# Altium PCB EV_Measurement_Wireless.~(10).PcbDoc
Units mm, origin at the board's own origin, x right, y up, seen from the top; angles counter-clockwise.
Board outline 152.4 x 101.6 mm, 4 copper layers (Top Layer, Mid-Layer 1, Mid_Layer 2, Bottom Layer), stack 0.605 mm thick; 59 components, 41 nets, 407 pads, 56 vias.
Unrouted connection lines stored in the file: 245.
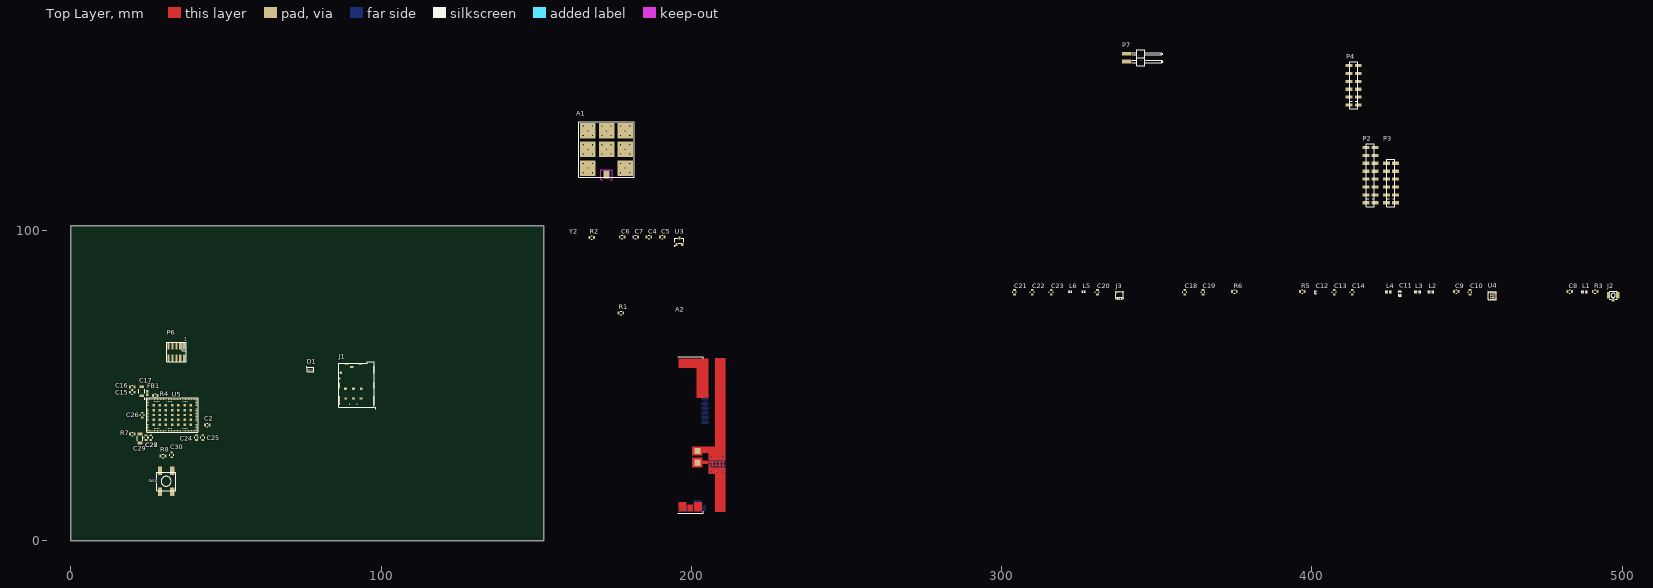
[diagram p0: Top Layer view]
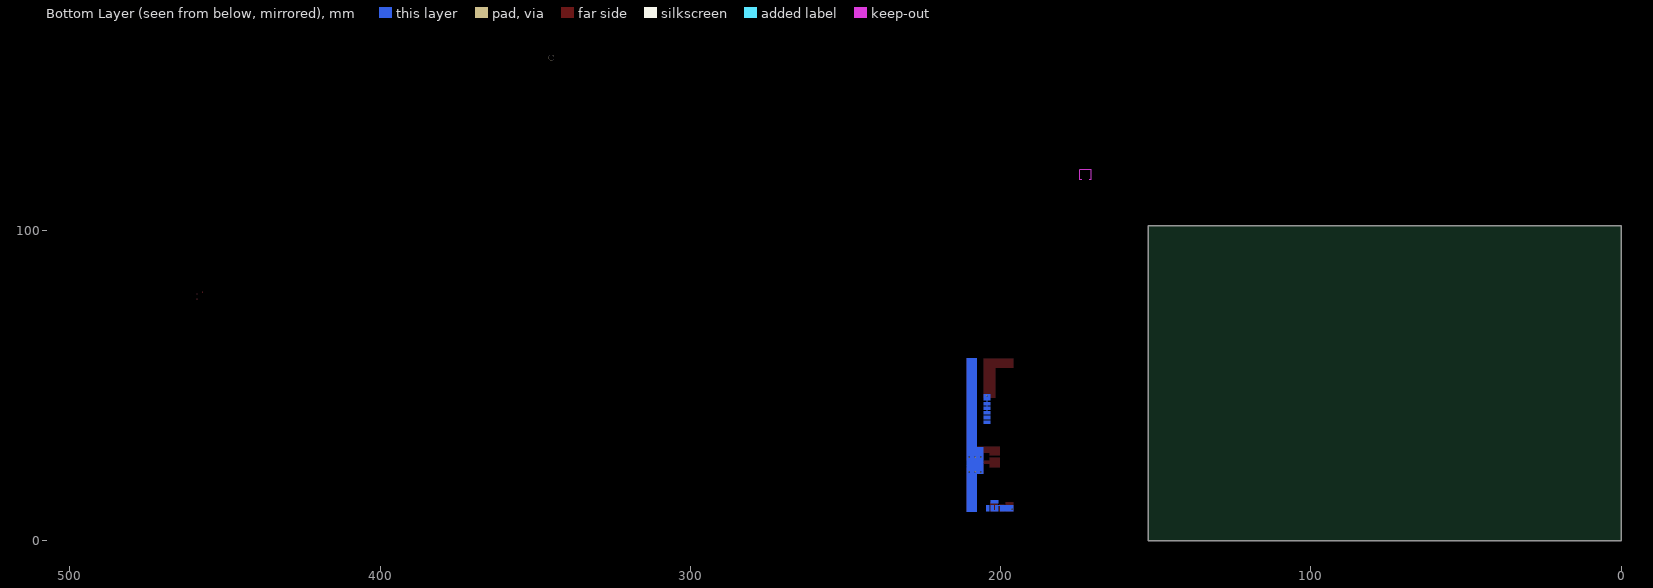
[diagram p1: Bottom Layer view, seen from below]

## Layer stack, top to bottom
Top Solder: solder mask 0.0102, Solder Resist, Dk 3.5
Top Layer: signal copper 0.0356
Dielectric 2: prepreg 0.0711, PP-006, Dk 4.1
Mid-Layer 1: signal copper 0.0356
Dielectric 1: prepreg 0.0711, PP-006, Dk 4.1
Mid_Layer 2: signal copper 0.0356
Dielectric2: dielectric 0.32, FR-4, Dk 4.1
Bottom Layer: signal copper 0.0356
Bottom Solder: solder mask 0.0102, Solder Resist, Dk 3.5

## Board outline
0,0 152.4,0 152.4,101.6 0,101.6

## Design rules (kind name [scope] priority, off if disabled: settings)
Clearance [All] p1: gap=0.254 ignorepadtopadclearanceinfootprint=FALSE
PolygonConnect [All] p1: connectstyle=Relief reliefconductorwidth=0.254 reliefentries=4 polygonreliefangle="90 Angle" airgapwidth=0.254
RoutingVias [All] p1: holewidth=0.711 width=1.27 viastyle="Through Hole" minholewidth=0.711 minwidth=1.27 maxholewidth=0.711 maxwidth=1.27
SolderMaskExpansion [All] p1: expansion=0.102 istentingtop=FALSE
SupplyNets "Schematic Supply Nets_5" [InNet('GND')] p1: voltage=0.000
SupplyNets "Schematic Supply Nets_4" [InNet('3V3')] p2: voltage=0.000
SupplyNets "Schematic Supply Nets_3" [InNet('VDD')] p3: voltage=0.000
SupplyNets "Schematic Supply Nets_2" [InNet('VDD_nRF')] p4: voltage=0.000
Width [All] p1: maxlimit=0.254 minlimit=0.254 preferedwidth=0.254
30 further rules are at their usual default settings.

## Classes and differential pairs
net class SWD: RESET SWDCLK SWDIO
net class GPIO: P0.13/AIN0 P0.14/AIN1 P0.15/AIN2 P0.16/AIN3 P0.17/AIN4 P0.18/AIN5
component class sheet4_sim_connections: C2 C4 C5 C6 C7 D1 J1 P2 P3 P4 P6 P7 R1 U3 Y2
component class sheet2_nRF9160: A1 A2 C8 C9 C10 C11 C12 C13 C14 C15 C16 C17 C18 C19 C20 C21 C22 C23 C24 C25 C26 C27 C28 C29 C30 FB1 J2 J3 L1 L2 L3 L4 L5 L6 R2 R3 R4 R5 R6 R7 R8 SW1 U4 U5

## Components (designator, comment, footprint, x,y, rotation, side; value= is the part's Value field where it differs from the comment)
A1 "DSGP.1575.18" DSGP.1575.18 172.648,126.135 r0 top
A2 "P822601" P822601 199.644,34.036 r90 top
C2 "10n" 0603(1608)C 43.942,37.338 r180 top
C4 "100n" 0603(1608)C 186.309,97.917 r0 top
C5 "100n" 0603(1608)C 190.627,97.917 r0 top
C6 "1u0" 0603(1608)C 177.673,97.917 r0 top
C7 "1u0" 0603(1608)C 181.991,97.917 r0 top
C8 "39p" 0603(1608)C 483.108,80.391 r0 top
C9 "39p" 0603(1608)C 446.532,80.391 r0 top
C10 "39p" 0603(1608)C 450.977,80.137 r90 top
C11 "N.C." CAPC1005X04L_NC 428.371,79.756 r90 top
C12 "N.C." CAPC0603X03L_C_NC 401.193,80.137 r90 top
C13 "100p" 0603(1608)C 407.162,80.137 r90 top
C14 "100n" 0603(1608)C 413.004,80.137 r90 top
C15 "39p" 0603(1608)C 19.812,47.879 r180 top
C16 "100n" 0603(1608)C 19.812,49.53 r180 top
C17 "47u" 1206(3216)C 22.86,48.186 r270 top
C18 "100n" 0603(1608)C 359.029,80.137 r90 top
C19 "100p" 0603(1608)C 364.871,80.137 r90 top
C20 "3.5" 0603(1608)C 330.835,80.137 r90 top value=4.3p
C21 "N.C" 0603(1608)C 304.165,80.137 r90 top
C22 "N.C." 0603(1608)C 309.88,80.137 r90 top
C23 "N.C." 0603(1608)C 315.976,80.137 r90 top
C24 "100n" 0603(1608)C 40.513,33.274 r90 top
C25 "4u7" 0603(1608)C 42.545,33.274 r90 top
C26 "4u7" 0603(1608)C 22.987,40.513 r90 top
C27 "15p" 0603(1608)C 24.257,33.274 r270 top value=39p
C28 "100n" 0603(1608)C 25.781,33.274 r270 top
C29 "47u" 1206(3216)C 22.352,33.02 r270 top
C30 "100n" 0603(1608)C 32.512,27.686 r90 top
D1 "CM1402" CM1402 77.204,55.191 r0 top
FB1 "BLM18EG221SN1D" BLM18SP221SN1B 24.638,47.665 r270 top
J1 "SF72S006VBAR2500" SF72S006VBAR2500 97.639,43.252 r0 top
J2 "MHF I Receptacle" "COAXIAL RF U.FL-R-SMT-1" 497.078,79.121 r0 top
J3 "MM8130-2600" COAXIAL-SWF 337.947,79.121 r0 top
L1 "68nH" INDC1005X04L_WW 487.807,80.264 r0 top
L2 "N.C." INDC1005X04L_NC 438.404,80.264 r0 top
L3 "N.C." INDC1005X04L_NC 434.086,80.264 r0 top
L4 "9.1nH" INDC1005X04L_WW 424.688,80.264 r0 top
L5 "1.5nH" INDC0603X03L_C 326.39,80.391 r0 top
L6 "22nH" INDC0603X03L_C 322.072,80.391 r0 top
P2 "Pin Header 2x6" LIST_1x8_SMD-NC 418.846,108.966 r90 top
P3 "Pin List 1x6" LIST_1x6_SMD-NC 425.45,108.966 r90 top
P4 "Socket 1x6" SOCKET_1x6_SMD 413.444,140.462 r90 top
P6 "Pin Header 2x5, 1.27mm" HDR_2x5-SMD-1.27mm-K 34.036,60.833 r180 top
P7 "Pin List 1x2, Angled" LIST_ANG_1x2-SMD-2.54MM 340.309,155.702 r90 top
R1 "N.C" 0603(1608) 177.292,73.406 r0 top value=0E
R2 "N.C" 0603(1608) 167.894,97.79 r0 top value=0E
R3 "0E" 0603(1608) 491.236,80.391 r0 top
R4 "10k" 0603(1608) 27.178,46.863 r0 top
R5 "0E" 0603(1608) 396.875,80.391 r0 top
R6 "1M" 0603(1608) 375.031,80.391 r0 top
R7 "N.C." 0603(1608) 19.812,34.417 r0 top value=0E
R8 "1k" 0603(1608) 29.706,27.305 r0 top
SW1 "PB SW" Switch-PB-6.2x6.3mm-SMD 30.734,19.177 r270 top
U3 "AP7333-33SAG-7" SOT-23A 195.199,95.504 r0 top
U4 "SKY65943-11" SKY65943-11 458.089,78.994 r0 top
U5 "nRF9160-SICAB1A" LGA50P1600X1050X104-161N 32.658,40.553 r0 top
Y2 "Shunt 2.54mm" Shunt_2.54mm_Horizontal 160.528,95.631 r0 top

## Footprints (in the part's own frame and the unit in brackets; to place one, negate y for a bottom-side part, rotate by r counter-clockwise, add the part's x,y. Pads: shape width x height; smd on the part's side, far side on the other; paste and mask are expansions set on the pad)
0603(1608) [mm] "Chip 0603 (1608 metric)"
  rect 0.6x0.9 smd: 1(-0.75,0) 2(0.75,0)
  silkscreen extent -0.2,-0.6 0.2,0.6, body extent -0.8,-0.4 0.8,0.4, height 0.3
0603(1608)C [mm] "Chip 0603 (1608 metric)"
  rect 0.6x0.9 smd: 1(-0.75,0) 2(0.75,0)
  silkscreen extent -0.2,-0.6 0.2,0.6, body extent -0.8,-0.38 0.8,0.42, height 0.5
1206(3216)C [mm] "Chip Capa 1206 (3216 metric)"
  rect 0.9x1.6 smd: 1(-1.45,0) 2(1.45,0)
  silkscreen extent -0.7,-0.9 0.7,0.9, body extent -1.6,-0.8 1.6,0.8, height 1
BLM18SP221SN1B [mm]
  rect 0.65x0.7 smd: 1(-0.675,0) 2(0.675,0)
  silkscreen extent 0,-0.3 0,0.3, body extent -0.8,-0.4 0.8,0.4, height 0.8
CAPC0603X03L_C_NC [mm]
  rect 0.27x0.3 smd mask+0.05: 1(-0.285,0) 2(0.285,0)
  silkscreen extent -0.49,-0.22 0.49,0.22
CAPC1005X04L_NC [mm]
  rect 0.6x0.5 smd: 1(-0.5,0) 2(0.5,0)
  silkscreen extent -0.9,-0.35 0.9,0.35
CM1402 [mm]
  round 0.25 smd mask+0.05: A1(-0.75,0.435) A2(-0.25,0.435) A3(0.25,0.435) A4(0.75,0.435) B1(-0.5,0) B2(0.5,0) C1(-0.75,-0.435) C2(-0.25,-0.435) C3(0.25,-0.435) C4(0.75,-0.435)
  silkscreen extent -1.28,-0.73 1.04,0.96, body extent -0.98,-0.66 0.98,0.66, height 0.72
"COAXIAL RF U.FL-R-SMT-1" [mm]
  rect 1x1.05 smd: 1(0,-1.525)
  rect 1.05x2.2 smd: 2(-1.475,0) 2(1.475,0)
  Top Layer pour cut-out: 0.85,1.3 -0.85,1.3 -0.85,-1.525 0.85,-1.525
  silkscreen extent -1.32,-1.3 1.28,1.3, body extent -1.5,-1.6 1.5,1.5, height 1.25
COAXIAL-SWF [mm]
  rect 0.5x0.58 smd: 1(0,1.16) 3(0,-1.16)
  rect 0.75x0.8 smd: 2(-1.025,-0.95) 2(-1.025,0.95) 2(1.025,-0.95) 2(1.025,0.95)
  Top Layer pour cut-out: -0.65,0.55 0.65,0.55 0.65,1.35 -0.65,1.35
  Top Layer pour cut-out: 0.65,-0.55 -0.65,-0.55 -0.65,-1.35 0.65,-1.35
  silkscreen extent -1.25,-1.25 1.25,1.25, body extent -1.26,-1.3 1.26,1.3, height 1.55
DSGP.1575.18 [mm]
  rect 2x2.5 smd paste-0.25 mask+0.1: 1(0,-8.1)
  rect 5x5 smd paste-0.6 mask+0.1: 2(-6,-6) 2(-6,0) 2(-6,6) 2(0,0) 2(0,6) 2(6,-6) 2(6,0) 2(6,6)
  round 0.35 on Mech16: 11(-7.5,-7.5) 11(-7.5,-4.5) 11(-7.5,-1.5) 11(-7.5,1.5) 11(-7.5,4.5) 11(-7.5,7.5) 11(-6,-6) 11(-6,0) 11(-6,6) 11(-4.5,-7.5) 11(-4.5,-4.5) 11(-4.5,-1.5) 11(-4.5,1.5) 11(-4.5,4.5) 11(-4.5,7.5) 11(-1.5,-1.5) 11(-1.5,1.5) 11(-1.5,4.5) 11(-1.5,7.5) 11(0,0) 11(0,6) 11(1.5,-1.5) 11(1.5,1.5) 11(1.5,4.5) 11(1.5,7.5) 11(4.5,-7.5) 11(4.5,-4.5) 11(4.5,-1.5) 11(4.5,1.5) 11(4.5,4.5) 11(4.5,7.5) 11(6,-6) 11(6,0) 11(6,6) 11(7.5,-7.5) 11(7.5,-4.5) 11(7.5,-1.5) 11(7.5,1.5) 11(7.5,4.5) 11(7.5,7.5)
  Keep-Out Layer lines w0.01: -1.26,-9.69 -1.84,-9.69 -1.84,-6.51 1.84,-6.51 1.84,-9.69 1.26,-9.69
  Multi-Layer pour cut-out: -2,-6.35 -2,-9.85 2,-9.85 2,-6.35
  silkscreen extent -9,-9 9,9, body extent -9,-9 9,9, height 4.03
HDR_2x5-SMD-1.27mm-K [mm]
  rect 0.76x2.4 smd: 1(-2.54,-1.95) 2(-2.54,1.95) 3(-1.27,-1.95) 4(-1.27,1.95) 5(0,-1.95) 6(0,1.95) 7(1.27,-1.95) 8(1.27,1.95) 9(2.54,-1.95) 10(2.54,1.95)
  silkscreen extent -3.18,-3.15 3.18,3.15, body extent -3.14,-2.92 3.14,2.92, height 6.11
INDC0603X03L_C [mm]
  rect 0.27x0.3 smd: 1(-0.285,0) 2(0.285,0)
  silkscreen extent -0.49,-0.22 0.49,0.22, body extent -0.31,-0.16 0.31,0.16, height 0.26
INDC1005X04L_NC [mm]
  rect 0.65x0.5 smd: 1(-0.475,0) 2(0.475,0)
  silkscreen extent -0.9,-0.35 0.9,0.35
INDC1005X04L_WW [mm]
  rect 0.65x0.5 smd: 1(-0.475,0) 2(0.475,0)
  silkscreen extent -0.9,-0.35 0.9,0.35, body extent -0.5,-0.3 0.5,0.3, height 0.51
LGA50P1600X1050X104-161N [mm]
  rect 0.54x0.54 smd mask+0.05: 1(-7.87,5.12) 21(-7.87,-5.12) 52(7.87,-5.12) 72(7.87,5.12)
  rect 0.54x0.3 smd mask+0.05: 2(-7.87,4.5) 3(-7.87,4) 4(-7.87,3.5) 5(-7.87,3) 6(-7.87,2.5) 7(-7.87,2) 8(-7.87,1.5) 9(-7.87,1) 10(-7.87,0.5) 11(-7.87,0) 12(-7.87,-0.5) 13(-7.87,-1) 14(-7.87,-1.5) 15(-7.87,-2) 16(-7.87,-2.5) 17(-7.87,-3) 18(-7.87,-3.5) 19(-7.87,-4) 20(-7.87,-4.5) 53(7.87,-4.5) 54(7.87,-4) 55(7.87,-3.5) 56(7.87,-3) 57(7.87,-2.5) 58(7.87,-2) 59(7.87,-1.5) 60(7.87,-1) 61(7.87,-0.5) 62(7.87,0) 63(7.87,0.5) 64(7.87,1) 65(7.87,1.5) 66(7.87,2) 67(7.87,2.5) 68(7.87,3) 69(7.87,3.5) 70(7.87,4) 71(7.87,4.5)
  rect 0.3x0.54 smd mask+0.05: 22(-7.25,-5.12) 23(-6.75,-5.12) 24(-6.25,-5.12) 25(-5.75,-5.12) 26(-5.25,-5.12) 27(-4.75,-5.12) 28(-4.25,-5.12) 29(-3.75,-5.12) 30(-3.25,-5.12) 31(-2.75,-5.12) 32(-2.25,-5.12) 33(-1.75,-5.12) 34(-1.25,-5.12) 35(-0.75,-5.12) 36(-0.25,-5.12) 37(0.25,-5.12) 38(0.75,-5.12) 39(1.25,-5.12) 40(1.75,-5.12) 41(2.25,-5.12) 42(2.75,-5.12) 43(3.25,-5.12) 44(3.75,-5.12) 45(4.25,-5.12) 46(4.75,-5.12) 47(5.25,-5.12) 48(5.75,-5.12) 49(6.25,-5.12) 50(6.75,-5.12) 51(7.25,-5.12) 73(7.25,5.12) 74(6.75,5.12) 75(6.25,5.12) 76(5.75,5.12) 77(5.25,5.12) 78(4.75,5.12) 79(4.25,5.12) 80(3.75,5.12) 81(3.25,5.12) 82(2.75,5.12) 83(2.25,5.12) 84(1.75,5.12) 85(1.25,5.12) 86(0.75,5.12) 87(0.25,5.12) 88(-0.25,5.12) 89(-0.75,5.12) 90(-1.25,5.12) 91(-1.75,5.12) 92(-2.25,5.12) 93(-2.75,5.12) 94(-3.25,5.12) 95(-3.75,5.12) 96(-4.25,5.12) 97(-4.75,5.12) 98(-5.25,5.12) 99(-5.75,5.12) 100(-6.25,5.12) 101(-6.75,5.12) 102(-7.25,5.12)
  rect 0.8x0.8 smd mask+0.05: 103(-6,-3.2) 103(-6,-1.6) 103(-6,0) 103(-6,1.6) 103(-6,3.2) 103(-4,-3.2) 103(-4,-1.6) 103(-4,0) 103(-4,1.6) 103(-4,3.2) 103(-2,-3.2) 103(-2,-1.6) 103(-2,0) 103(-2,1.6) 103(-2,3.2) 103(0,-3.2) 103(0,-1.6) 103(0,0) 103(0,1.6) 103(0,3.2) 103(2,-3.2) 103(2,-1.6) 103(2,0) 103(2,1.6) 103(2,3.2) 103(4,-3.2) 103(4,-1.6) 103(4,0) 103(4,1.6) 103(4,3.2) 103(6,-3.2) 103(6,-1.6) 103(6,0) 103(6,1.6) 103(6,3.2)
  rect 0.3x0.3 smd mask+0.05: 104(-5.75,-4.35) 105(-5.25,-4.35) 106(-4.75,-4.35) 107(-4.25,-4.35) 108(-1.75,-4.35) 109(-1.25,-4.35) 110(-0.75,-4.35) 111(-0.25,-4.35) 112(3.25,-4.35) 113(3.75,-4.35) 114(4.25,-4.35) 115(4.75,-4.35) 116(4.75,4.35) 117(4.25,4.35) 118(3.75,4.35) 119(3.25,4.35) 120(-0.25,4.35) 121(-0.75,4.35) 122(-1.25,4.35) 123(-1.75,4.35) 124(-4.25,4.35) 125(-4.75,4.35) 126(-5.25,4.35) 127(-5.75,4.35)
  Top Layer pour cut-out: -8.15,5.4 8.15,5.4 8.15,-5.4 -8.15,-5.4
  silkscreen extent -9.05,-5.5 8.25,5.5, body extent -8.05,-5.3 8.05,5.3, height 1.2
LIST_1x6_SMD-NC [mm]
  rect 1.02x2.19 smd: 1(0,1.465) 1(0,-1.465) 2(2.54,-1.465) 2(2.54,1.465) 3(5.08,-1.465) 3(5.08,1.465) 4(7.62,-1.465) 4(7.62,1.465) 5(10.16,-1.465) 5(10.16,1.465) 6(12.7,-1.465) 6(12.7,1.465)
  silkscreen extent -1.27,-1.27 13.97,1.27
LIST_1x8_SMD-NC [mm]
  rect 1.02x2.19 smd: 1(0,1.465) 1(0,-1.465) 2(2.54,-1.465) 2(2.54,1.465) 3(5.08,-1.465) 3(5.08,1.465) 4(7.62,-1.465) 4(7.62,1.465) 5(10.16,-1.465) 5(10.16,1.465) 6(12.7,-1.465) 6(12.7,1.465) 7(15.24,-1.465) 7(15.24,1.465) 8(17.78,-1.465) 8(17.78,1.465)
  silkscreen extent -1.27,-1.27 19.05,1.27
LIST_ANG_1x2-SMD-2.54MM [mm]
  round 1.78 hole 1.78 unplated: 0(0,-4.496)
  rect 1.27x3.18 smd: 1(-1.27,0) 2(1.27,0)
  silkscreen extent -2.54,-11.58 2.54,-1.8, body extent -2.56,-11.61 2.52,1.35, height 3.03
P822601 [mm]
  rect 2x2 smd: 1(-8.89,-2.286) 2(-5.08,-2.286)
  Top Layer region: -10.45,-11.296 -24.65,-11.296 -24.65,-7.996 -10.45,-7.996
  Top Layer region: 24.75,-11.296 -8.05,-11.296 -8.05,-8.001 24.75,-8.001
  Top Layer region: -8.45,-10.496 -8.95,-10.496 -8.95,-10.296 -8.45,-10.296
  Top Layer region: -9.45,-10.496 -9.95,-10.496 -9.95,-10.296 -9.45,-10.296
  Top Layer region: -8.45,-10.696 -9.95,-10.696 -9.95,-10.496 -8.45,-10.496
  Top Layer region: -8.45,-10.896 -8.95,-10.896 -8.95,-10.696 -8.45,-10.696
  Top Layer region: -9.45,-10.896 -9.95,-10.896 -9.95,-10.696 -9.45,-10.696
  Top Layer region: -9.6,-11.296 -9.8,-11.296 -9.8,-10.896 -9.6,-10.896
  Top Layer region: -7.3,-3.796 -10.4,-3.796 -10.4,-0.596 -7.3,-0.596
  Top Layer region: -8.2,-5.696 -9.2,-5.696 -9.2,-3.796 -8.2,-3.796
  Top Layer region: -8.6,-6.896 -8.8,-6.896 -8.8,-5.696 -8.6,-5.696
  Top Layer region: -8.45,-7.096 -8.95,-7.096 -8.95,-6.896 -8.45,-6.896
  Top Layer region: -9.45,-7.096 -9.95,-7.096 -9.95,-6.896 -9.45,-6.896
  Top Layer region: -8.45,-7.296 -9.95,-7.296 -9.95,-7.096 -8.45,-7.096
  Top Layer region: -8.45,-7.496 -8.95,-7.496 -8.95,-7.296 -8.45,-7.296
  Top Layer region: -9.45,-7.496 -9.95,-7.496 -9.95,-7.296 -9.45,-7.296
  Top Layer region: -9.2,-6.496 -12.45,-6.496 -12.45,-5.996 -9.2,-5.996
  Top Layer region: -10.45,-7.996 -12.45,-7.996 -12.45,-6.496 -10.45,-6.496
  Top Layer region: -3.67,-3.826 -6.399,-3.826 -6.4,-0.566 -3.67,-0.566
  Top Layer region: -3.67,-5.996 -5.71,-5.996 -5.71,-3.826 -3.67,-3.826
  Top Layer region: -3.67,-7.991 -8.05,-7.991 -8.05,-5.996 -3.67,-5.996
  Top Layer region: 24.6,-2.046 21.7,-2.046 21.7,3.754 24.6,3.754
  Top Layer region: 24.6,-5.796 12.05,-5.796 12.05,-2.046 24.6,-2.046
  Top Layer region: -21.6,-3.746 -24.5,-3.746 -24.5,-1.246 -21.6,-1.246
  Top Layer region: -22.4,-0.846 -24.5,-0.846 -24.5,0.854 -22.4,0.854
  Top Layer region: -21.6,1.254 -24.5,1.254 -24.5,3.754 -21.6,3.754
  Top Layer region: -9.45,-9.796 -9.95,-9.796 -9.95,-9.596 -9.45,-9.596
  Top Layer region: -8.45,-9.796 -8.95,-9.796 -8.95,-9.596 -8.45,-9.596
  Top Layer region: -8.45,-9.596 -9.95,-9.596 -9.95,-9.396 -8.45,-9.396
  Top Layer region: -9.45,-9.396 -9.95,-9.396 -9.95,-9.196 -9.45,-9.196
  Top Layer region: -8.45,-9.396 -8.95,-9.396 -8.95,-9.196 -8.45,-9.196
  Top Layer region: -9.6,-9.196 -9.8,-9.196 -9.8,-8.596 -9.6,-8.596
  Top Layer region: -9.45,-8.596 -9.95,-8.596 -9.95,-8.396 -9.45,-8.396
  Top Layer region: -8.45,-8.596 -8.95,-8.596 -8.95,-8.396 -8.45,-8.396
  Top Layer region: -8.45,-8.396 -9.95,-8.396 -9.95,-8.196 -8.45,-8.196
  Top Layer region: -9.45,-8.196 -9.95,-8.196 -9.95,-7.996 -9.45,-7.996
  Top Layer region: -8.45,-8.196 -8.95,-8.196 -8.95,-7.996 -8.45,-7.996
  Bottom Layer region: 24.752,-11.296 -24.648,-11.296 -24.65,-7.996 24.75,-7.996
  Bottom Layer region: -3.86,-7.996 -12.45,-7.996 -12.45,-5.996 -3.86,-5.996
  Bottom Layer region: 4.7,-5.796 3.7,-5.796 3.7,-3.746 4.7,-3.746
  Bottom Layer region: 6.2,-5.796 5.2,-5.796 5.2,-3.746 6.2,-3.746
  Bottom Layer region: 13.2,-4.596 11.2,-4.596 11.2,-3.746 13.2,-3.746
  Bottom Layer region: 10.7,-4.596 9.7,-4.596 9.7,-3.746 10.7,-3.746
  Bottom Layer region: 9.2,-4.596 8.2,-4.596 8.2,-3.746 9.2,-3.746
  Bottom Layer region: 7.7,-4.596 6.7,-4.596 6.7,-3.746 7.7,-3.746
  Bottom Layer region: 13.2,-4.896 6.7,-4.896 6.7,-4.596 13.2,-4.596
  Bottom Layer region: 13.2,-5.796 11.2,-5.796 11.2,-4.896 13.2,-4.896
  Bottom Layer region: 10.7,-5.796 9.7,-5.796 9.7,-4.896 10.7,-4.896
  Bottom Layer region: 9.2,-5.796 8.2,-5.796 8.2,-4.896 9.2,-4.896
  Bottom Layer region: 7.7,-5.796 6.7,-5.796 6.7,-4.896 7.7,-4.896
  Bottom Layer region: -22.5,-5.046 -24.5,-5.046 -24.5,-4.046 -22.5,-4.046
  Bottom Layer region: -21,-3.546 -22,-3.546 -22,-1.046 -21,-1.046
  Bottom Layer region: -22.5,-0.546 -24.5,-0.546 -24.5,3.754 -22.5,3.754
  Bottom Layer region: -22.5,-1.046 -22.8,-1.046 -22.8,-0.546 -22.5,-0.546
  Bottom Layer region: -22.5,-2.046 -24.5,-2.046 -24.5,-1.046 -22.5,-1.046
  Bottom Layer region: -24.196,-2.546 -24.5,-2.546 -24.5,-2.046 -24.196,-2.046
  Bottom Layer region: -22.5,-3.546 -24.5,-3.546 -24.5,-2.546 -22.5,-2.546
  Multi-Layer pour cut-out: -39.95,5.08 39.05,5.08 39.05,-7.996 -39.95,-7.996
  silkscreen extent -25.2,-4.25 25.3,4.05, body extent -24.95,-4 25.05,4, height 3.2
SF72S006VBAR2500 [mm]
  rect 0.45x2.9 smd: 0(-11.175,1.9) 0(0,1.9)
  rect 0.45x1.9 smd: 0(-11.175,6.75) 0(0,6.75)
  rect 0.75x0.7 smd: 0(-10.675,10.9)
  rect 1.4x0.5 smd: 0(-8.78,13.85) 0(-4.38,13.85)
  rect 0.3x0.6 smd: 0(-7.8,0.75) 0(-5.36,0.75)
  rect 0.45x2.4 smd: 0(0,11.9)
  rect 0.9x0.7 smd: C1(-4.14,2.6) C2(-6.58,2.6) C3(-9.02,2.6) C5(-4.04,5.77) C6(-6.58,5.77) C7(-9.12,5.77)
  rect 0.6x0.6 smd: CSW(-10.95,9.1)
  rect 1.2x0.65 smd: DSW(-7.13,12.775)
  Top Layer pour cut-out: -10.084,9.5 -3.073,9.5 -3.073,-0.025 -10.084,-0.025
  Top Layer pour cut-out: -8.407,13.106 -3.48,13.106 -3.48,9.855 -8.407,9.855
  silkscreen extent -11.3,-0.67 0.67,14.53, body extent -11.2,0.05 0.02,14.4, height 1.25
Shunt_2.54mm_Horizontal [mm]
  body extent 0,-2.54 5.03,2.54, height 3.04
SKY65943-11 [mm]
  rect 0.425x0.515 smd mask+0.05: 1(-1.188,1.144) 5(-1.188,-1.144) 6(1.188,-1.144) 10(1.188,1.144)
  rect 0.425x0.275 smd mask+0.05: 2(-1.188,0.5) 3(-1.188,0) 4(-1.188,-0.5) 7(1.188,-0.5) 8(1.188,0) 9(1.188,0.5)
  rect 1.45x2.802 smd paste-2 mask-5: 11(0,0)
  rect 1.55x2.487 on Top Solder: ""(0,0)
  Top Layer region: -0.988,0.887 -0.713,0.887 -0.713,1.4 -0.988,1.4
  Top Layer region: 0.712,-1.4 0.987,-1.4 0.987,-0.887 0.712,-0.887
  Top Layer region: 0.712,0.363 0.987,0.363 0.987,0.637 0.712,0.637
  Top Layer region: -0.712,-0.362 -0.987,-0.362 -0.987,-0.637 -0.712,-0.637
  silkscreen extent -1.65,-1.3 1.3,1.65, body extent -1.25,-1.25 1.25,1.25, height 0.71
SOCKET_1x6_SMD [mm]
  rect 1.02x2.19 smd: 1(0,1.465) 1(0,-1.465) 2(2.54,-1.465) 2(2.54,1.465) 3(5.08,-1.465) 3(5.08,1.465) 4(7.62,-1.465) 4(7.62,1.465) 5(10.16,-1.465) 5(10.16,1.465) 6(12.7,1.465) 6(12.7,-1.465)
  silkscreen extent -1.27,-1.27 13.97,1.27, body extent -1.27,-2.29 13.97,2.29, height 7.47
SOT-23A [mil]
  rect 30x40 smd: 1(0,0) 2(74.8,0) 3(37.4,82.68)
  silkscreen extent -27,-21 94,79, body extent -20,-5 95,87, height 39
Switch-PB-6.2x6.3mm-SMD [mm]
  rect 2.75x1.4 smd: 1(-3.375,2) 1(3.375,2) 2(-3.375,-2) 2(3.375,-2)
  silkscreen extent -3,-3 3,3, body extent -4,-3 4,3.3, height 3.1

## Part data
A1: library part DSGP.1575.18.4.A.02, "18 x 18 mm Low Profile GPS L1 / GALILEO E1 Passive Patch Antenna", Manufacturer=Taoglas, Part number IPS=00000004435, Part number Norautron=N.A., Supplier Part Number 1=931-1511-1-ND
A2: "ANTENNA PRESTTA OCTABAND LTE", Manufacturer=Ethertronics, Part number IPS=00000009001, Part number Norautron=N.A.
C2: library part C0603_4_10n_25V, "Cer Chip Capacitor / 10n/ +-5%/ 25V", Capacitance=10nF, Case Code (Imperial)=0603, Case Code (Metric)=1608, Dielectric=X7R, Dielectric Material=Ceramic, Manufacturer 1=KEMET, Manufacturer Part Number=C0603C103M3RACTU, Max Operating Temperature=125°C, Min Operating Temperature=-55°C, Package Quantity=1, Special Value 1=+-5%, Special Value 2=25V, Supplier Part Number 1=399-8989-1-ND, Tolerance=20%
C4 C5 C14 C16 C18 C24 C28 C30: library part C0603_5_100n_25V, "Cer Chip Capacitor / 100n/ +-5%/ 25V", Capacitance=100nF, Case Code (Imperial)=0603, Case Code (Metric)=1608, Dielectric=X7R, Manufacturer 1=Yageo, Manufacturer Part Number=CC0603KRX7R8BB104, Max Operating Temperature=125°C, Min Operating Temperature=-55°C, Package Quantity=1, Special Value 1=+-5%, Special Value 2=25V, Supplier Part Number 1=311-1341-1-ND, Tolerance=10%
C6 C7: library part C0603_6_1u0_25V, "Cer Chip Capacitor / 1u0 / +-10%/ 25V", Capacitance=1uF, Case Code (Imperial)=0603, Case Code (Metric)=1608, Manufacturer 1=Samsung, Manufacturer Part Number=CL10B105KA8VPNC, Max Operating Temperature=125°C, Min Operating Temperature=-55°C, Special Value 1=+-10%, Special Value 2=25V, Supplier Part Number 1=1276-6617-1-ND, Tolerance=10%
C8 C9 C10: library part C0603_1_39p_50V, "Cer Chip Capacitor / 39p/ +-1%/ 50V", Manufacturer=Murata, Manufacturer P/N=GCM1885C1H390FA16J, Special Value 1=+-1%, Special Value 2=50V
C11: library part C0402-N.C., "Not mounted", Manufacturer=N.A.
C12: library part C0201-N.C., "Not mounted", Manufacturer=N.A.
C13 C19: library part C0603_2_100p_50V, "Cer Chip Capacitor / 100p/ +-1%/ 50V", Manufacturer=Murata, Manufacturer P/N=GCM1885C1H101FA16D, Special Value 1=+-1%, Special Value 2=50V
C15 C27: library part C0603_1_39p_50V, "Cer Chip Capacitor / 15p/ +-1%/ 50V", Manufacturer=Murata, Manufacturer P/N=GCM1885C1H390FA16J, Special Value 1=+-1%, Special Value 2=50V
C17 C29: library part C1206_7_47u_6.3V, "Cer Chip Capacitor / 47u/ +-10%/ 6.3V", Capacitance=47uF, Case Code (Imperial)=1206, Case Code (Metric)=3216, Dielectric=X5R, Manufacturer 1=Samsung, Manufacturer Part Number=CL31A476MQHNNNE, Max Operating Temperature=85°C, Min Operating Temperature=-55°C, Package Quantity=1, Special Value 1=+-20%, Special Value 2=6.3V, Supplier Part Number 1=1276-1167-1-ND, Tolerance=20%
C20: library part C0603_0_4.3p_50V, "Cer Chip Capacitor / 3.5p/ +-1%/ 50V", Special Value 1=+-1%, Special Value 2=50V, Supplier Part Number 1=490-6096-1-ND
C21 C22 C23: library part C0603, "Cer Chip Capacitor"
C25 C26: library part C0603_6_4u7_25V, "Cer Chip Capacitor / 4u7/ +-10%/ 25V", Capacitance=4.7uF, Case Code (Imperial)=0603, Case Code (Metric)=1608, Dielectric=X5R, Manufacturer 1=Samsung, Manufacturer Part Number=CL10A475MA8NQNC, Max Operating Temperature=85°C, Min Operating Temperature=-55°C, Package Quantity=1, Special Value 1=+-10%, Special Value 2=25V, Supplier Part Number 1=1276-1903-1-ND, Tolerance=20%
D1: "EMI Network Filter Arrays SIM CARD EMI FILTER WITH ESD PROTECTION", Manufacturer="ON Semiconductor", Manufacturer Part Number=CM1402-03CP, Part number IPS=00000009949, Part number Norautron=N.A., Supplier Part Number 1=CM1402-03CPOSTR-ND
FB1: "Ferrite Bead", Manufacturer_Name="Murata Electronics", Mouser Part Number=81-BLM18EG221SN1D
J1: "n 8 (6 + 2) Position Card Connector NANO SIM Surface Mount, Right Angle Gold", Manufacturer="JAE Electronics", Part number IPS=00000009956, Part number Norautron=N.A., Supplier Part Number 1=670-2799-1-ND
J2: library part 20279-001E-03, "Ultraminiature Coaxial Connector, 50 Ohm, SMD", Manufacturer=Wellshow, Part number IPS=00000004436, Part number Norautron=N.A.
J3: "Coaxial Connector with Switch", Manufacturer=Murata, Part number IPS=00000009955, Part number Norautron=N.A., Supplier Part Number 1=490-4981-1-ND
L1: library part L0402-68n-Wirewound-Murata, "Inductor, 140mA, ±2%, 1960mΩ, Q=20", Manufacturer=Murata, Manufacturer Part Number=LQW15AN68NG00, Part number IPS=00000002494, Part number Norautron=N.A., Supplier Part Number 1=490-6837-1-ND
L2 L3: library part L0402-N.C., "Not mounted", Manufacturer=N.A.
L4: library part L0402-9n1-Wirewound-Murata, "Inductor, 540mA, ±2%, 140mΩ, Q=25", Manufacturer=Murata, Manufacturer Part Number=LQW15AN9N1G00, Part number IPS=00000002497, Part number Norautron=N.A., Supplier Part Number 1=490-6854-1-ND
L5: library part L0201-1n5, "Inductor, 650mA, ±0.1nH", Manufacturer=Murata, Manufacturer Part Number=LQP03TQ1N5B02D, Part number IPS=00000000836, Part number Norautron=N.A.
L6: library part L0201-22n, "Chip Inductor", Manufacturer=N.A., Part number IPS=00000001478
P2: library part "Pin Header 2x6, N.C.", "Pin Header 2x6, 2.54mm (100mil)", Manufacturer=N.A.
P3: library part "Pin List 1x6 SMD, N.C.", "Pin List 1x6, 2.54mm (100mil), SMD", Manufacturer=W-CON, Manufacturer Part Number=1125-1106S0M116R2, Part number IPS=N.A.
P4: library part "Socket 1x6 SMD", "Socket 1x6, 2.54mm (100mil), SMD", Manufacturer=W-CON, Manufacturer Part Number=2171-106MS0CUNR1, Part number IPS=00000009964, Part number Norautron=N.A.
P6: library part "Pin Header 2x5 SMD, 1.27mm, KS", "Pin Header 2x5, 1.27mm (50mil), SMD, Keying Shroud", Manufacturer=W-CON, Manufacturer Part Number=3132-10MS0BK00R1, Part number IPS=00000009968, Part number Norautron=N.A.
P7: library part "Pin List Ang 1x2 SMD, 2.54mm", "Pin List 1x2, 2.54mm (100mil), Right Angled, SMD", Manufacturer=W-CON, Manufacturer Part Number=1125B-1102S0Z135R2, Part number IPS=00000009972, Part number Norautron=N.A.
R1 R2 R3 R5 R7: library part R0603_0_0E, "Chip Resistor / 0E / 1% / 50V / 100mW / 0603(1608)", Case Code (Imperial)=0603, Case Code (Metric)=1608, Manufacturer 1=Panasonic, Manufacturer Part Number=ERJ-3GEY0R00V, Max Operating Temperature=155°C, Max Power Dissipation=100mW, Min Operating Temperature=-55°C, Package Quantity=1, Resistance=0mR, Special Value 1=1%, Special Value 2=50V, Supplier Part Number 1=311-0.0HRCT-ND, Temperature Coefficient=600ppm/°C, Tolerance=0%, Voltage Rating=75V
R4: library part R0603_4_10k, "Chip Resistor / 10k/ 1% / 50V / 100mW / 0603(1608)", Case Code (Imperial)=0603, Case Code (Metric)=1608, Manufacturer 1=Susumu, Manufacturer Part Number=RR0816P-103-D, Max Operating Temperature=125°C, Max Power Dissipation=63mW, Min Operating Temperature=-55°C, Package Quantity=1, Resistance=10kR, Special Value 1=1%, Special Value 2=50V, Special Value 3=100mW, Supplier Part Number 1=RR08P10.0KDCT-ND, Temperature Coefficient=25ppm/°C, Tolerance=0.5%, Voltage Rating=75V
R6: library part R0603_6_1M, "Chip Resistor / 1M/ 1% / 50V / 100mW / 0603(1608)", Case Code (Imperial)=1206, Case Code (Metric)=3216, Manufacturer Part Number=ERJ-8ENF1004V, Max Operating Temperature=155°C, Max Power Dissipation=250mW, Min Operating Temperature=-55°C, Package Quantity=1, Resistance=1MR, Special Value 1=1%, Special Value 2=50V, Special Value 3=100mW, Supplier Part Number 1=311-1.00MHRCT-ND, Temperature Coefficient=100ppm/°C, Voltage Rating=200V
R8: library part R0603_3_1k, "Chip Resistor / 1k/ 1% / 50V / 100mW / 0603(1608)", Case Code (Imperial)=1206, Case Code (Metric)=3216, Manufacturer=Panasonic, Manufacturer Part Number=ERA-8AEB102V, Max Operating Temperature=155°C, Max Power Dissipation=250mW, Min Operating Temperature=-55°C, Package Quantity=5000, Resistance=1kR, Special Value 1=1%, Special Value 2=50V, Special Value 3=100mW, Supplier Part Number 1=P1.0KDBCT-ND, Temperature Coefficient=25ppm/°C, Tolerance=0.1%, Voltage Rating=150V
SW1: library part Switch-PB-6.2x6.3mm-SMD, "Tactile Switch, SPNO, SMD, 160gf, 6.2x6.3x2.5mm", Manufacturer=Dailywell, Manufacturer Part Number=TS604VM1-025BR-R, Part number IPS=00000007812, Part number Norautron=N.A.
U3: "300mA, Low Quiescent Current, Fast Transient Low Dropout Linear Regulator", Manufacturer="Diodes Incorporated", Part number IPS=00000001673, Part number Norautron=N.A., Supplier Part Number 1=AP7333-33SAG-7DICT-ND
U4: "GNSS Low-Noise Amplifier Front-End Module with Integrated Pre-Filter and Post-Filter", Manufacturer=Skyworks, Part number IPS=00000002997, Part number Norautron=N.A., Supplier Part Number 1=863-2032-1-ND
U5: "Low power System-in-Package with integrated LTE-M/NB-IoT modem and GPS", Manufacturer="Nordic Semiconductor", Part number IPS=80000002329, Part number Norautron=N.A.
Y2: library part "SHUNT JUMPER 2.54mm BLACK GOLD Horizontal (Obsolete)", "Shunt Jumper 2.54mm Black", Manufacturer=N.A., Part number IPS=00000001916, Supplier Part Number 1="S9001-ND, or similar"

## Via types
v1: diameter 0.35, hole 0.15, Top Layer to Mid-Layer 1, 48 vias
v2: diameter 0.5, hole 0.25, Top Layer to Bottom Layer, 8 vias

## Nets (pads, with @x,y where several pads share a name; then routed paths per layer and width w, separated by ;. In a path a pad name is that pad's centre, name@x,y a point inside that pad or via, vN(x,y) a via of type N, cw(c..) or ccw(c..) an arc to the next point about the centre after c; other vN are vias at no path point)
3V3: C7.1 C8.2 L1.1 U3.2
ANT: C21.2 J3.3 L5.1
DEC0: C26.1 U5.13
GND: A1.2 A2.2 C2.2 C4.2 C5.1 C6.2 C7.2 C8.1 C11.2 C12.1 C13.1 C14.1 C15.2 C16.2 C17.2 C18.1 C19.1 C21.1 C22.1 C23.1 C24.2 C25.2 C26.2 C27.2 C28.2 C29.2 C30.2 D1.B1 D1.B2 J1.0 J1.C5 J2.2 J3.2 L3.2 L6.1 P2.1 P2.3 P2.5 P2.7 P6.3 P6.5 P6.9 R6.1 SW1.1 U3.3 U4.1 U4.4 U4.6 U4.9 U4.11 U5.1 U5.5 U5.6 U5.7 U5.8 U5.9 U5.11 U5.14 U5.17 U5.21 U5.27 U5.31 U5.36 U5.41 U5.44 U5.47 U5.50 U5.52 U5.56 U5.60 U5.62 U5.63 U5.65 U5.66 U5.68 U5.69 U5.72 U5.74 U5.75 U5.76 U5.77 U5.78 U5.79 U5.80 U5.81 U5.82 U5.85 U5.90 U5.94 U5.98 U5.103
  other v1: 457.789,78.094 458.389,78.094 457.789,78.694 458.389,78.694 457.789,79.294 458.389,79.294 457.789,79.894 458.389,79.894 165.148,118.635 168.148,118.635 177.148,118.635 180.148,118.635 166.648,120.135 178.648,120.135 165.148,121.635 168.148,121.635 177.148,121.635 180.148,121.635 165.148,124.635 168.148,124.635 171.148,124.635 174.148,124.635 177.148,124.635 180.148,124.635 166.648,126.135 172.648,126.135 178.648,126.135 165.148,127.635 168.148,127.635 171.148,127.635 174.148,127.635 177.148,127.635 180.148,127.635 165.148,130.635 168.148,130.635 171.148,130.635 174.148,130.635 177.148,130.635 180.148,130.635 166.648,132.135 172.648,132.135 178.648,132.135 165.148,133.635 168.148,133.635 171.148,133.635 174.148,133.635 177.148,133.635 180.148,133.635
  other v2: 206.39,22.15 208.194,22.196 210.11,22.196 206.39,26.986 208.194,26.986 210.11,26.986
GPS_EN: R5.1 R6.2 U5.93
GPS_RF1: C9.2 U5.67
GPS_RF2: C9.1 C10.2 J2.1 L1.2 L2.1
GPS_RF3: C10.1 U4.10
GPS_RF4: L3.1 R3.1 U4.5
GPS_RF7: A1.1 C11.1 R3.2
LTE_RF1: J3.1 U5.61
NetA2_1: A2.1 C20.2 L6.2
NetC2_1: C2.1 D1.A4 J1.C1
NetC12_2: C12.2 L2.2
NetC13_2: C13.2 C14.2 R2.1 U4.3
NetC18_2: C18.2 C19.2 R5.2 U4.2
NetC20_1: C20.1 C22.2 C23.2 L5.2
NetC27_1: C27.1 C28.1 C29.1 R7.2 U5.22
NetC30_1: C30.1 R8.2 U5.32
NetD1_A1: D1.A1 J1.C2
NetD1_A2: D1.A2 J1.C3
NetD1_A3: D1.A3 J1.C7
NetFB1_2: FB1.2 R4.1 U5.102
NetL4_1: L4.1 U4.8
NetL4_2: L4.2 U4.7
NetR4_2: R4.2 U5.101
P0.13/AIN0: P2.2 P3.1 P4.1 U5.23
P0.14/AIN1: P2.4 P3.2 P4.2 U5.24
P0.15/AIN2: P2.6 P3.3 P4.3 U5.25
P0.16/AIN3: P2.8 P3.4 P4.4 U5.26
P0.17/AIN4: P3.5 P4.5 U5.28
P0.18/AIN5: P3.6 P4.6 U5.29
RESET: P6.10 R8.1 SW1.2
SIM_1V8: U5.49
SIM_CLK: U5.46
SIM_IO: U5.48
SIM_RST: U5.43
SWDCLK: P6.4 U5.33
SWDIO: P6.2 U5.34
VDD: C4.1 C5.2 C6.1 C24.1 C25.1 P6.1 P7.2 R1.2 R2.2 U3.1 U5.12
VDD_nRF: C15.1 C16.1 C17.1 FB1.1 P7.1 R1.1 R7.1
pads on no net: A1.11 D1.C1 D1.C2 D1.C3 D1.C4 J1.C6 J1.CSW J1.DSW P6.6 P6.7 P6.8 P7.0 U4. U5.2 U5.3 U5.4 U5.10 U5.15 U5.16 U5.18 U5.19 U5.20 U5.30 U5.35 U5.37 U5.38 U5.39 U5.40 U5.42 U5.45 U5.51 U5.53 U5.54 U5.55 U5.57 U5.58 U5.59 U5.64 U5.70 U5.71 U5.73 U5.83 U5.84 U5.86 U5.87 U5.88 U5.89 U5.91 U5.92 U5.95 U5.96 U5.97 U5.99 U5.100 U5.104 U5.105 U5.106 U5.107 U5.108 U5.109 U5.110 U5.111 U5.112 U5.113 U5.114 U5.115 U5.116 U5.117 U5.118 U5.119 U5.120 U5.121 U5.122 U5.123 U5.124 U5.125 U5.126 U5.127
copper on no net:
  other v2: 196.39,10.186 204.44,46.736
